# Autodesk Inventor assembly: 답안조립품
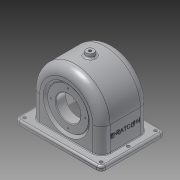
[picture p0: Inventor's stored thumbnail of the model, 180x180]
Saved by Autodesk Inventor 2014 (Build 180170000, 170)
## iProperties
Created: 2015-09
Part Number: 답안조립품
Document SubType Name: Assembly
Designer: Administrator
Author: Administrator
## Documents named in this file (2)
- C:\Users\Administrator\Desktop\450907V1042\답안조립품.iam
- C:\Users\Administrator\Desktop\450907V1042\1-본체.ipt
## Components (1 placed, 1 different names)
1. 1-본체:1
